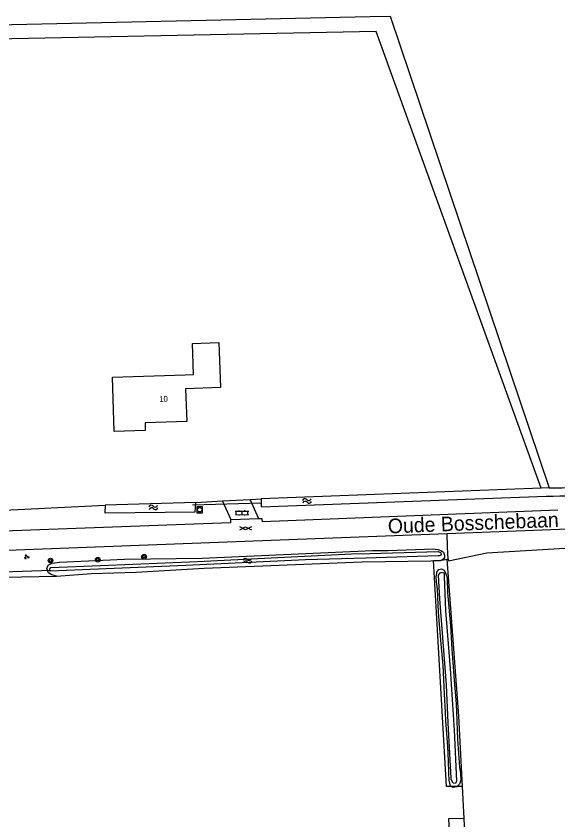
# Model space of a CAD drawing. Extents: x 137000 to 140001, y 403500 to 406000.
# Drawn here: x 138151.9 to 138245, y 405497.8 to 405635.7 of the extents above; entities that cross this region are included whole.
import ezdxf

# ---------------------------------------------------------------- set-up
doc = ezdxf.new("R2010")
doc.units = 0
for name, color, linetype in [('gg-afsc-draadraster', 7, 'Continuous'), ('gg-afsc-lijn draadraster', 7, 'Continuous'), ('gg-anno-huisnummerreeks BGT', 7, 'Continuous'), ('gg-anno-openbare ruimte label', 7, 'Continuous'), ('gg-bbg-gedigitaliseerde bebouwing', 7, 'Continuous'), ('gg-bbg-hoofdgebouw', 7, 'Continuous'), ('gg-knt-bronhoudergrens', 7, 'Continuous'), ('gg-knt-verharding', 7, 'Continuous'), ('gg-kntw-bovenkant insteek waterloop', 7, 'Continuous'), ('gg-kntw-waterlijn', 7, 'Continuous'), ('gg-kwrk-duiker nz buis', 7, 'Continuous'), ('gt-grn-groengrens', 7, 'Continuous'), ('gt-grn-vlakafsluiter', 7, 'Continuous'), ('gt-grn-weggrens', 7, 'Continuous'), ('gt-symb-boom', 7, 'Continuous'), ('gt-symb-gesloten verharding', 7, 'Continuous'), ('gt-symb-groenvak', 7, 'Continuous'), ('gt-symb-klinker verharding', 7, 'Continuous'), ('gt-symb-rioolschacht', 7, 'Continuous'), ('gt-symb-watersymbool', 7, 'Continuous')]:
    doc.layers.add(name, color=color, linetype=linetype)

# ---------------------------------------------------------------- blocks, each defined once
blk = doc.blocks.new('gt0-KL1')
at = {"layer": 'gt-symb-klinker verharding'}
for p, q in [((-1.15, 0.3), (1.15, 0.3)), ((-1, -0.3), (-1, 0.3)), ((-0.5, 0.3), (-0.5, 0.45)), ((0, -0.3), (0, 0.3)), ((0.5, 0.3), (0.5, 0.45)), ((1, -0.3), (1, 0.3)), ((-1.15, -0.3), (1.15, -0.3)), ((-0.5, -0.45), (-0.5, -0.3)), ((0.5, -0.45), (0.5, -0.3))]:
    blk.add_line(p, q, dxfattribs=at)
blk = doc.blocks.new('gt0-WA')
at = {"layer": 'gt-symb-watersymbool'}
for centre, start, end in [((-0.32, 0.02), 28.0725, 151.9275), ((0.43, 0.42), 208.0725, 331.9275), ((-0.32, -0.43), 28.0725, 151.9275), ((0.43, -0.03), 208.0725, 331.9275)]:
    blk.add_arc(centre, 0.425, start, end, dxfattribs=at)
blk = doc.blocks.new('gt0-GESVH1')
at = {"layer": 'gt-symb-gesloten verharding'}
for p, q in [((-0.99, -0.26), (0.01, 0.24)), ((0.01, -0.26), (-0.99, 0.24)), ((0.01, 0.24), (1.01, -0.26)), ((1.01, 0.24), (0.01, -0.26))]:
    blk.add_line(p, q, dxfattribs=at)
blk = doc.blocks.new('gt0-GRVAK')
at = {"layer": 'gt-symb-groenvak'}
for p, q in [((-0.11, 0.19), (-0.23, 0.24)), ((-0.18, 0.15), (0.09, 0.15)), ((-0.09, 0.21), (-0.16, 0.32)), ((-0.05, 0.21), (-0.05, 0.39)), ((0, 0.21), (0.06, 0.32)), ((0.01, 0.19), (0.13, 0.24)), ((0.26, -0.05), (0.2, 0.06)), ((0.3, -0.05), (0.3, 0.13)), ((0.35, -0.05), (0.41, 0.06)), ((-0.24, -0.23), (-0.36, -0.18)), ((-0.32, -0.26), (-0.05, -0.26)), ((-0.23, -0.21), (-0.29, -0.09)), ((-0.18, -0.2), (-0.18, -0.02)), ((-0.14, -0.21), (-0.07, -0.09)), ((-0.12, -0.23), (0, -0.18)), ((0.24, -0.07), (0.12, -0.02)), ((0.17, -0.11), (0.44, -0.11)), ((0.37, -0.07), (0.49, -0.02))]:
    blk.add_line(p, q, dxfattribs=at)
blk = doc.blocks.new('gt0-BOOM')
at = {"layer": 'gt-symb-boom'}
for radius in [0.4, 0.2]:
    blk.add_circle((0, 0), radius, dxfattribs=at)
blk = doc.blocks.new('gt0-RS')
at = {"layer": 'gt-symb-rioolschacht'}
blk.add_lwpolyline([(-0.5, -0.5), (0.5, -0.5), (0.5, 0.5), (-0.5, 0.5)], close=True, dxfattribs=at)
blk.add_circle((0, 0), 0.375, dxfattribs=at)

msp = doc.modelspace()

# ---------------------------------------------------------------- linework, layer by layer
at = {"layer": 'gg-afsc-draadraster'}
for p, q in [((138228.59, 405503.53), (138228.88, 405498.03)), ((138228.88, 405498.03), (138229.52, 405486.1))]:
    msp.add_line(p, q, dxfattribs=at)
msp.add_lwpolyline([(138225.98, 405542.51), (138227.94, 405515.58), (138228.59, 405503.53)], dxfattribs=at)
at = {"layer": 'gg-afsc-lijn draadraster'}
for p, q in [((138228.59, 405503.53), (138228.88, 405498.03)), ((138228.88, 405498.03), (138229.52, 405486.1))]:
    msp.add_line(p, q, dxfattribs=at)
for points in [[(138226.23, 405542.25), (138232.8, 405543.63), (138285.47, 405546.77)], [(138228.59, 405503.53), (138225.89, 405503.53), (138223.66, 405542.28)], [(138225.98, 405542.51), (138227.94, 405515.58), (138228.59, 405503.53)], [(138228.88, 405498.03), (138226.25, 405497.95), (138226.87, 405486.19), (138226.99, 405483.84), (138227.69, 405467.87)]]:
    msp.add_lwpolyline(points, dxfattribs=at)
at = {"layer": 'gg-bbg-gedigitaliseerde bebouwing'}
for points in [[(138180.98, 405574.19), (138182.42, 405574.22), (138182.23, 405579.55), (138186.79, 405579.71), (138187.06, 405571.97)], [(138168.82, 405564.43), (138168.5, 405573.76), (138180.98, 405574.19)]]:
    msp.add_lwpolyline(points, dxfattribs=at)
at = {"layer": 'gg-bbg-hoofdgebouw'}
for points in [[(138187.06, 405571.97), (138181.07, 405571.76), (138181.26, 405566.16)], [(138181.26, 405566.16), (138174.1, 405565.91), (138174.15, 405564.61), (138168.82, 405564.43)]]:
    msp.add_lwpolyline(points, dxfattribs=at)
at = {"layer": 'gg-knt-bronhoudergrens'}
for p, q in [((138225.98, 405542.51), (138226.21, 405542.55)), ((138226.21, 405542.55), (138226.23, 405542.25))]:
    msp.add_line(p, q, dxfattribs=at)
at = {"layer": 'gg-knt-verharding'}
for p, q in [((138188.89, 405549.3), (138187.44, 405552.53)), ((138193.64, 405549.43), (138192.18, 405552.79)), ((138193.64, 405549.43), (138188.89, 405549.3))]:
    msp.add_line(p, q, dxfattribs=at)
for points in [[(138245.04, 405550.95), (138194.26, 405548.97), (138194.22, 405549.45), (138193.64, 405549.43)], [(138188.89, 405549.3), (138188.77, 405549.28), (138188.79, 405548.75), (138148.21, 405547.31)], [(138225.99, 405546.93), (138245.3, 405547.66), (138256.45, 405548.11)], [(138055.47, 405540.04), (138055.61, 405540.07), (138055.82, 405540.42), (138085.42, 405541.61), (138225.99, 405546.93)]]:
    msp.add_lwpolyline(points, dxfattribs=at)
at = {"layer": 'gg-kntw-bovenkant insteek waterloop'}
for p, q in [((138212.76, 405635.67), (138216.22, 405635.74)), ((138216.22, 405635.74), (138243.52, 405554.77)), ((138242.19, 405554.73), (138194.03, 405552.89)), ((138243.52, 405554.77), (138242.19, 405554.73)), ((138182.83, 405552.28), (138167.27, 405551.83)), ((138225.07, 405542.35), (138224.92, 405542.33))]:
    msp.add_line(p, q, dxfattribs=at)
for points in [[(138063.2, 405630.11), (138061.31, 405630.07), (138061.43, 405632.32), (138212.76, 405635.67)], [(138242.19, 405554.73), (138213.84, 405633.09), (138134.11, 405631.51)], [(138194.03, 405552.89), (138194.06, 405551.49), (138243.04, 405553.36)], [(138167.27, 405551.83), (138167.2, 405550.49), (138182.69, 405550.65), (138182.83, 405552.28)], [(138158.9, 405539.63), (138158.11, 405539.86), (138157.51, 405540.18), (138157.23, 405540.91), (138157.47, 405541.48), (138158.12, 405541.83), (138159.4, 405542.02), (138170.6, 405542.51), (138183.94, 405542.69), (138213.19, 405544.05), (138215.9, 405544.02), (138222.1, 405544.25), (138223.5, 405544.3), (138224.41, 405544.22), (138224.94, 405544.04), (138225.2, 405543.85), (138225.37, 405543.73), (138225.56, 405543.23), (138225.56, 405542.81), (138225.36, 405542.52), (138225.07, 405542.35)], [(138158.9, 405539.63), (138159.64, 405539.7), (138164.88, 405540.08), (138172.58, 405540.33), (138184.27, 405540.98), (138211.42, 405542.05), (138223.21, 405542.27), (138223.66, 405542.28)], [(138223.66, 405542.28), (138224.02, 405542.29), (138224.53, 405542.29), (138224.66, 405542.29), (138224.92, 405542.33)], [(138224.84, 405529.28), (138224.54, 405533.41), (138224.42, 405536.08), (138224.36, 405537.47), (138224.18, 405538.63), (138224.11, 405539.49), (138224.28, 405540.41), (138224.58, 405540.74), (138225.03, 405540.89), (138225.47, 405540.62), (138225.78, 405539.99), (138225.92, 405539.68), (138225.99, 405539.19), (138226.05, 405536.79), (138226.57, 405531.12), (138226.84, 405527.1), (138227.14, 405522.5), (138227.56, 405517.67), (138227.59, 405516.35), (138227.77, 405511.66), (138228.14, 405506.82), (138228.3, 405505.74), (138228.36, 405504.59), (138228.14, 405503.89), (138227.67, 405503.44), (138227.07, 405503.32), (138226.57, 405503.6), (138226.38, 405504.62), (138226.29, 405505.84), (138226.22, 405507.92), (138226.12, 405510.37), (138225.76, 405514.86), (138225.73, 405516.24), (138225.55, 405519.43), (138225.33, 405524.29), (138224.84, 405529.28)]]:
    msp.add_lwpolyline(points, dxfattribs=at)
for centre, radius, start, end in [((138242.11, 405761.38), 206.62, 270.3927, 275.4202), ((138241.88, 405761.19), 207.83, 270.3196, 275.481)]:
    msp.add_arc(centre, radius, start, end, dxfattribs=at)
at = {"layer": 'gg-kntw-waterlijn'}
for points in [[(138157.88, 405540.49), (138157.72, 405540.65), (138157.72, 405540.88), (138157.92, 405541.09), (138166.48, 405541.44), (138183.12, 405542.15), (138209.59, 405543.44), (138212.72, 405543.52), (138224.47, 405543.83), (138224.87, 405543.7), (138224.99, 405543.46), (138224.96, 405543.25), (138224.76, 405543.11), (138224.48, 405543.12), (138212.02, 405542.73), (138201.66, 405542.4), (138181.1, 405541.47), (138157.88, 405540.49)], [(138226.53, 405508.08), (138226.2, 405514.46), (138225.91, 405520.94), (138224.76, 405535.75), (138224.55, 405539.77), (138224.8, 405540.21), (138225.16, 405540.28), (138225.49, 405540.14), (138225.51, 405539.57), (138225.73, 405533.7), (138226.52, 405523.69), (138227.2, 405513.17), (138227.64, 405504.41), (138227.45, 405504.03), (138227.07, 405504.09), (138226.72, 405504.74), (138226.69, 405504.95), (138226.53, 405508.08)]]:
    msp.add_lwpolyline(points, dxfattribs=at)
at = {"layer": 'gg-kwrk-duiker nz buis'}
for p, q in [((138182.27, 405551.84), (138194.11, 405552.23)), ((138157.98, 405540.6), (138149.67, 405540.33))]:
    msp.add_line(p, q, dxfattribs=at)
at = {"layer": 'gt-grn-groengrens'}
for p, q in [((138146.72, 405550.8), (138167.27, 405551.83)), ((138182.83, 405552.28), (138187.44, 405552.53)), ((138192.18, 405552.79), (138194.03, 405552.89)), ((138226.08, 405544.59), (138225.99, 405546.93)), ((138226.21, 405542.55), (138226.08, 405544.59))]:
    msp.add_line(p, q, dxfattribs=at)
msp.add_lwpolyline([(138226.23, 405542.25), (138232.8, 405543.63), (138285.47, 405546.77)], dxfattribs=at)
at = {"layer": 'gt-grn-vlakafsluiter'}
msp.add_line((138149.84, 405539.42), (138158.9, 405539.63), dxfattribs=at)
msp.add_lwpolyline([(138225.07, 405542.35), (138225.4, 405542.41), (138225.72, 405542.47), (138225.98, 405542.51)], dxfattribs=at)
at = {"layer": 'gt-grn-weggrens'}
msp.add_line((138187.44, 405552.53), (138192.18, 405552.79), dxfattribs=at)

# ---------------------------------------------------------------- block references
at = {"layer": 'gt-symb-boom'}
for p in [(138173.95, 405542.96), (138157.86, 405542.29), (138165.99, 405542.43)]:
    msp.add_blockref('gt0-BOOM', p, dxfattribs=at)
at = {"layer": 'gt-symb-gesloten verharding'}
msp.add_blockref('gt0-GESVH1', (138191.37, 405547.85), dxfattribs=at)
at = {"layer": 'gt-symb-groenvak'}
msp.add_blockref('gt0-GRVAK', (138153.75, 405542.93), dxfattribs=at)
at = {"layer": 'gt-symb-klinker verharding', "rotation": 0.973934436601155}
msp.add_blockref('gt0-KL1', (138190.77, 405550.47), dxfattribs=at)
at = {"layer": 'gt-symb-rioolschacht'}
msp.add_blockref('gt0-RS', (138183.49, 405551.01), dxfattribs=at)
at = {"layer": 'gt-symb-watersymbool'}
for p, rotation in [((138201.87, 405552.52), 11.006664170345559), ((138175.48, 405551.41), 11.00666417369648), ((138191.63, 405542.26), 11.00666417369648)]:
    msp.add_blockref('gt0-WA', p, dxfattribs=dict(at, rotation=rotation))

# ---------------------------------------------------------------- texts
at = {"layer": 'gg-anno-huisnummerreeks BGT'}
msp.add_text('10', height=1, rotation=2, dxfattribs=at).set_placement((138176.55, 405569.5))
at = {"layer": 'gg-anno-openbare ruimte label'}
msp.add_text('Oude Bosschebaan', height=2.5, rotation=2.2, dxfattribs=at).set_placement((138215.87, 405546.95))

doc.saveas('drawing.dxf')
